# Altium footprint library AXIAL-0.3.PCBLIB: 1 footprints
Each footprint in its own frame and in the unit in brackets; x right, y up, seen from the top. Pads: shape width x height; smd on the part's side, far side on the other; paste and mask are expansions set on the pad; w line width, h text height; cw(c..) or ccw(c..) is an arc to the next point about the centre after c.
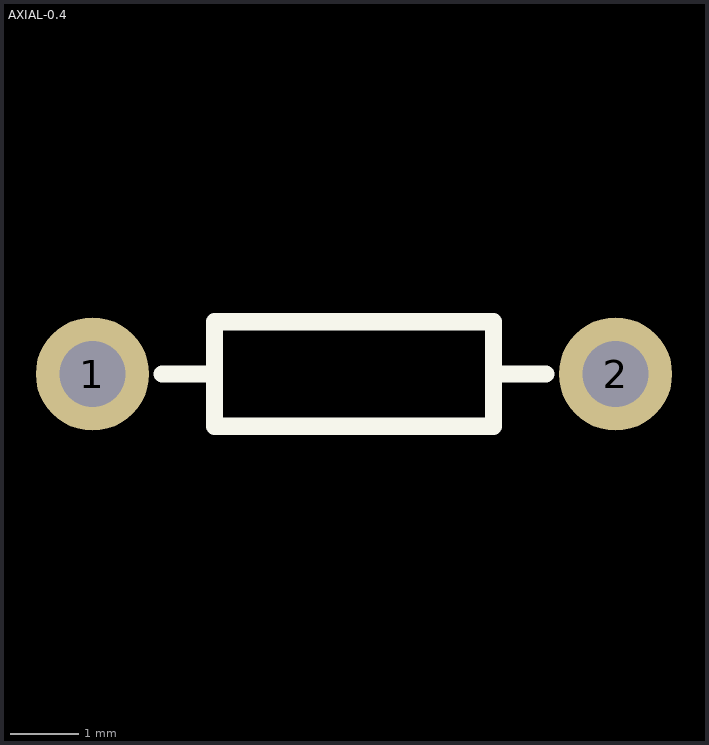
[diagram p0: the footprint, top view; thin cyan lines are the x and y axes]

## AXIAL-0.4 [mil] "www.ouravr.com"
pads (2):
  round 65 hole 38: 1(-32300,-23900) 2(-32000,-23900)
Top Overlay:
  lines w10: -32260,-23900 -32230,-23900 ; -32070,-23900 -32040,-23900 ; -32230,-23900 -32230,-23930 -32070,-23930 -32070,-23870 -32230,-23870 -32230,-23900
